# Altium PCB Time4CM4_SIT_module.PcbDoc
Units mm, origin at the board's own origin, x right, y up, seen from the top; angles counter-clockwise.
Board outline 11.4 x 15 mm, 4 copper layers (Top Layer, Int1 (GND), Int2 (PWR), Bottom Layer), stack 1.56 mm thick; 13 components, 16 nets, 71 pads, 34 vias.
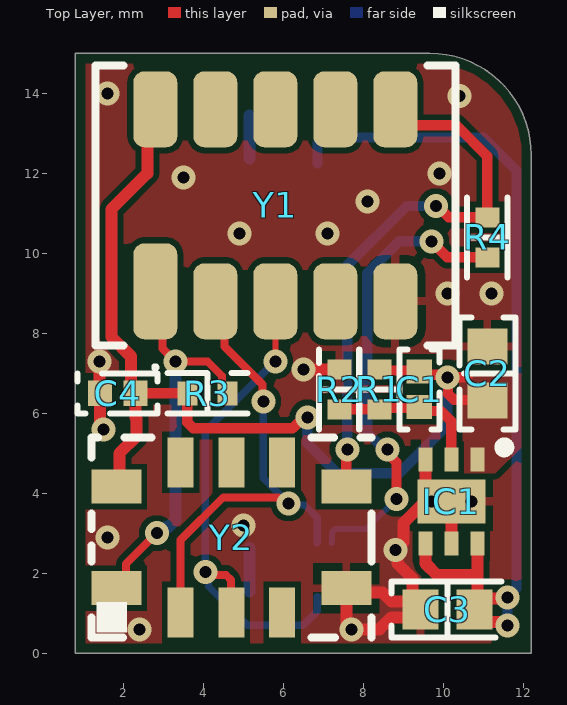
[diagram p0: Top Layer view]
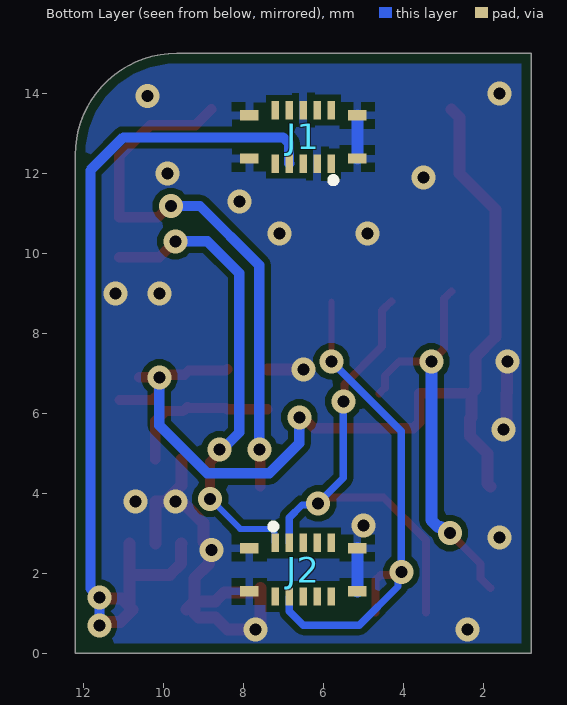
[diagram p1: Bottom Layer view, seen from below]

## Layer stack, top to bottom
Top Solder: solder mask 0.0254, SM-001, Dk 4
Top Layer: signal copper 0.035
Dielectric 1: prepreg 0.055, PP-017, Dk 4.3
Dielectric 2: prepreg 0.055, PP-017, Dk 4.3
Int1 (GND): signal copper 0.035
Dielectric 3: core 1.2, Core-039, Dk 4.8
Int2 (PWR): signal copper 0.035
Dielectric 4: prepreg 0.055, PP-017, Dk 4.3
Dielectric 5: prepreg 0.055, PP-017, Dk 4.3
Bottom Layer: signal copper 0.035
Bottom Solder: solder mask 0.0254, SM-001, Dk 4

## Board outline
0.8,0 0.8,15 9.66,15 cw(c9.66,12.46) 12.2,12.46 12.2,0

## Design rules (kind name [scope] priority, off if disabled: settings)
AcuteAngle [All] p1: minimum=3.50000000000000E+0001 checktracksonly=FALSE
BoardOutlineClearance "BoardOutlineClearance 1" [All] p1: gap=0.25 ignorepadtopadclearanceinfootprint=FALSE except(0: Arc-SplitContinuation Track-SplitContinuation SMDPad-SplitContinuation THPad-SplitContinuation Via-SplitContinuation Fill-SplitContinuation Poly-SplitContinuation Region-SplitContinuation Text-SplitContinuation) // Milling
BoardOutlineClearance "BoardOutlineClearance 2" [All] p2: gap=0.4 ignorepadtopadclearanceinfootprint=FALSE except(0: Arc-SplitContinuation Track-SplitContinuation SMDPad-SplitContinuation THPad-SplitContinuation Via-SplitContinuation Fill-SplitContinuation Poly-SplitContinuation Region-SplitContinuation Text-SplitContinuation) // V-Cut
Clearance "Clearance 3 Oz" [All] p1 off: gap=0.35 ignorepadtopadclearanceinfootprint=FALSE except(0.25: Arc-Hole Track-Hole SMDPad-Hole THPad-Hole Via-Hole Fill-Hole Poly-Hole Region-Hole Text-Hole)
Clearance "Clearance 2 Oz" [All] p2 off: gap=0.3 ignorepadtopadclearanceinfootprint=FALSE except(0.25: Arc-Hole Track-Hole SMDPad-Hole THPad-Hole Via-Hole Fill-Hole Poly-Hole Region-Hole Text-Hole)
Clearance "Clearance-1 1 Oz" [All] p3 off: gap=0.2 ignorepadtopadclearanceinfootprint=FALSE except(0.25: Arc-Hole Track-Hole SMDPad-Hole THPad-Hole Via-Hole Fill-Hole Poly-Hole Region-Hole Text-Hole) // Standart
Clearance "Clearance-2 1 Oz" [All] p4 off: gap=0.15 ignorepadtopadclearanceinfootprint=FALSE except(0.2: Arc-Fill Arc-Poly Track-Fill Track-Poly SMDPad-Fill SMDPad-Poly THPad-Fill THPad-Poly Via-Fill Via-Poly Fill-Fill Fill-Poly Poly-Poly; 0.25: Arc-Hole Track-Hole SMDPad-Hole THPad-Hole Via-Hole Fill-Hole Poly-Hole Region-Hole Text-Hole) // Advance
Clearance "Clearance-1 1/2 Oz" [All] p5 off: gap=0.125 ignorepadtopadclearanceinfootprint=FALSE except(0.2: Arc-Fill Arc-Poly Track-Fill Track-Poly SMDPad-SMDPad SMDPad-Fill SMDPad-Poly THPad-Fill THPad-Poly Via-Fill Via-Poly Fill-Fill Fill-Poly Poly-Poly Poly-Region Poly-Text; 0.25: Arc-Hole Track-Hole SMDPad-Hole THPad-Hole Via-Hole Fill-Hole Poly-Hole Region-Hole Text-Hole) // Standart
Clearance "Clearance-2 1/2 Oz" [All] p6: gap=0.1 ignorepadtopadclearanceinfootprint=FALSE except(0.15: Arc-Fill Arc-Poly Track-Fill Track-Poly SMDPad-SMDPad SMDPad-Fill SMDPad-Poly THPad-Fill THPad-Poly Via-Fill Via-Poly Fill-Fill Fill-Poly Poly-Poly Poly-Region Poly-Text; 0.25: Arc-Hole Track-Hole SMDPad-Hole THPad-Hole Via-Hole Fill-Hole Poly-Hole Region-Hole Text-Hole) // Advance
DiffPairsRouting "DiffPairsRouting 1 Oz" [All] p1: maxlimit=0.254 minlimit=0.2 mostfreqgap=0.254 toplayer_minwidth=0.2 toplayer_maxwidth=0.381 toplayer_prefwidth=0.381 midlayer1_minwidth=0.2 midlayer1_maxwidth=0.381 midlayer1_prefwidth=0.381 midlayer2_minwidth=0.2 midlayer2_maxwidth=0.381 midlayer2_prefwidth=0.381 bottomlayer_minwidth=0.2 bottomlayer_maxwidth=0.381 bottomlayer_prefwidth=0.381 maxuncoupledlength=12.7
DiffPairsRouting "DiffPairsRouting 1/2 Oz" [All] p2: maxlimit=0.254 minlimit=0.1 mostfreqgap=0.254 toplayer_minwidth=0.1 toplayer_maxwidth=0.381 toplayer_prefwidth=0.381 midlayer1_minwidth=0.1 midlayer1_maxwidth=0.381 midlayer1_prefwidth=0.381 midlayer2_minwidth=0.1 midlayer2_maxwidth=0.381 midlayer2_prefwidth=0.381 bottomlayer_minwidth=0.1 bottomlayer_maxwidth=0.381 bottomlayer_prefwidth=0.381 maxuncoupledlength=12.7
HoleSize "Minimum HoleSize" [IsPad] p1: absolutevalues=TRUE maxlimit=5.9 minlimit=0.6 maxpercent=80.000 minpercent=20.000
HoleSize "Minimum HoleSize VIA 1" [IsVia] p2: absolutevalues=TRUE maxlimit=5.9 minlimit=0.3 maxpercent=80.000 minpercent=20.000 // Standart
HoleSize "Minimum HoleSize VIA 2" [IsVia] p3: absolutevalues=TRUE maxlimit=5.9 minlimit=0.2 maxpercent=80.000 minpercent=20.000 // Advance
HoleToHoleClearance Hole2HoleClearance [All] p1: gap=0.25 allowstackedmicrovias=FALSE
MinimumAnnularRing "Minimum AR VIA Standart" [IsVia] p1: minimumring=0.15
MinimumAnnularRing "Minimum AR PAD Standart" [IsPAD] p2: minimumring=0.2
MinimumAnnularRing "Minimum AR VIA Advance" [IsVia] p3: minimumring=0.1
MinimumAnnularRing "Minimum AR PAD Advance" [IsPAD] p4: minimumring=0.15
MinimumSolderMaskSliver "SolderMask Bridge Standart" [All] p1: minsoldermaskwidth=0.15 // All Masks
MinimumSolderMaskSliver "SolderMask Bridge Advance" [All] p2: minsoldermaskwidth=0.1 // Mask LDI
PlaneClearance "PlaneClearance 3 Oz" [All] p1: clearance=0.35
PlaneClearance "PlaneClearance 2 Oz" [All] p2: clearance=0.3
PlaneClearance "PlaneClearance 1 Oz" [All] p3: clearance=0.2
PlaneClearance "PlaneClearance-1 1/2 Oz" [All] p4: clearance=0.2 // Standart
PlaneClearance "PlaneClearance-2 1/2 Oz" [All] p5: clearance=0.15 // Advance
PlaneConnect "TermalConnect 3 Oz" [All] p1: planeconnectstyle=Relief reliefexpansion=0.2 reliefentries=4 reliefconductorwidth=0.35 reliefairgap=0.35 // Standart
PlaneConnect "TermalConnect 2 Oz" [All] p2: planeconnectstyle=Relief reliefexpansion=0.2 reliefentries=4 reliefconductorwidth=0.3 reliefairgap=0.3 // Standart
PlaneConnect "TermalConnect-1 1 Oz" [All] p3: planeconnectstyle=Relief reliefexpansion=0.2 reliefentries=4 reliefconductorwidth=0.2 reliefairgap=0.2 // Standart
PlaneConnect "TermalConnect-2 1 Oz" [All] p4: pad.planeconnectstyle=Relief pad.reliefexpansion=0.15 pad.reliefentries=4 pad.reliefconductorwidth=0.2 pad.reliefairgap=0.2 via.planeconnectstyle=Direct via.reliefexpansion=0.15 via.reliefentries=4 via.reliefconductorwidth=0.15 via.reliefairgap=0.15 // Advance
PlaneConnect "TermalConnect-1 1/2 Oz" [All] p5: planeconnectstyle=Relief reliefexpansion=0.2 reliefentries=4 reliefconductorwidth=0.2 reliefairgap=0.2 // Standart
PlaneConnect "TermalConnect-2 1/2 Oz" [All] p6: pad.planeconnectstyle=Relief pad.reliefexpansion=0.15 pad.reliefentries=4 pad.reliefconductorwidth=0.15 pad.reliefairgap=0.15 via.planeconnectstyle=Direct via.reliefexpansion=0.15 via.reliefentries=4 via.reliefconductorwidth=0.15 via.reliefairgap=0.15 // Advance
PolygonConnect "PolygonConnect 3 Oz" [All] p1 off: thpad.connectstyle=Relief thpad.reliefconductorwidth=0.35 thpad.reliefentries=4 thpad.polygonreliefangle="90 Angle" thpad.airgapwidth=0.35 smdpad.connectstyle=Relief smdpad.reliefconductorwidth=0.35 smdpad.reliefentries=4 smdpad.polygonreliefangle="90 Angle" smdpad.airgapwidth=0.35 via.connectstyle=Direct via.reliefconductorwidth=0.254 via.reliefentries=4 via.polygonreliefangle="90 Angle" via.airgapwidth=0.254
PolygonConnect "PolygonConnect 2 Oz" [All] p2 off: thpad.connectstyle=Relief thpad.reliefconductorwidth=0.3 thpad.reliefentries=4 thpad.polygonreliefangle="90 Angle" thpad.airgapwidth=0.3 smdpad.connectstyle=Relief smdpad.reliefconductorwidth=0.3 smdpad.reliefentries=4 smdpad.polygonreliefangle="90 Angle" smdpad.airgapwidth=0.3 via.connectstyle=Direct via.reliefconductorwidth=0.254 via.reliefentries=4 via.polygonreliefangle="90 Angle" via.airgapwidth=0.254
PolygonConnect "PolygonConnect-1 1 Oz" [All] p3 off: thpad.connectstyle=Relief thpad.reliefconductorwidth=0.2 thpad.reliefentries=4 thpad.polygonreliefangle="90 Angle" thpad.airgapwidth=0.2 smdpad.connectstyle=Relief smdpad.reliefconductorwidth=0.2 smdpad.reliefentries=4 smdpad.polygonreliefangle="90 Angle" smdpad.airgapwidth=0.2 via.connectstyle=Direct via.reliefconductorwidth=0.254 via.reliefentries=4 via.polygonreliefangle="90 Angle" via.airgapwidth=0.254 // Standart
PolygonConnect "PolygonConnect-2 1 Oz" [All] p4 off: thpad.connectstyle=Relief thpad.reliefconductorwidth=0.15 thpad.reliefentries=4 thpad.polygonreliefangle="90 Angle" thpad.airgapwidth=0.15 smdpad.connectstyle=Relief smdpad.reliefconductorwidth=0.15 smdpad.reliefentries=4 smdpad.polygonreliefangle="90 Angle" smdpad.airgapwidth=0.15 via.connectstyle=Direct via.reliefconductorwidth=0.254 via.reliefentries=4 via.polygonreliefangle="90 Angle" via.airgapwidth=0.254 // Advance
PolygonConnect "PolygonConnect-1 1/2 Oz" [All] p5: thpad.connectstyle=Relief thpad.reliefconductorwidth=0.15 thpad.reliefentries=4 thpad.polygonreliefangle="90 Angle" thpad.airgapwidth=0.2 smdpad.connectstyle=Relief smdpad.reliefconductorwidth=0.2 smdpad.reliefentries=4 smdpad.polygonreliefangle="90 Angle" smdpad.airgapwidth=0.2 via.connectstyle=Direct via.reliefconductorwidth=0.254 via.reliefentries=4 via.polygonreliefangle="90 Angle" via.airgapwidth=0.254 // Standart
PolygonConnect "PolygonConnect-2 1/2 Oz" [All] p6: thpad.connectstyle=Relief thpad.reliefconductorwidth=0.125 thpad.reliefentries=4 thpad.polygonreliefangle="90 Angle" thpad.airgapwidth=0.15 smdpad.connectstyle=Relief smdpad.reliefconductorwidth=0.125 smdpad.reliefentries=4 smdpad.polygonreliefangle="90 Angle" smdpad.airgapwidth=0.15 via.connectstyle=Direct via.reliefconductorwidth=0.254 via.reliefentries=4 via.polygonreliefangle="90 Angle" via.airgapwidth=0.254 // Advance
RoutingCorners [All] p1 off: cornerstyle=45-Degree minsetback=2.54 maxsetback=2.54
RoutingVias [All] p1: holewidth=0.3 width=0.6 viastyle="Through Hole" minholewidth=0.2 minwidth=0.4 maxholewidth=0.5 maxwidth=1
SilkToSilkClearance Silk2SilkClearance [All] p1 off: silktosilkclearance=0.15
SilkToSolderMaskClearance Silk2SolderMaskClearance [IsPad] p1 off: minsilkscreentomaskgap=0.15 clearancetoexposedcopper=TRUE
SolderMaskExpansion SolderMaskExpansion-1 [All] p1: expansion=0.05 istentingtop=FALSE // Standart
SolderMaskExpansion "SolderMaskExpansion LDI" [All] p2: expansion=0.025 istentingtop=FALSE // Advance
UnRoutedNet [All] p1: checkbadconnections=TRUE
Width "Width 3 Oz" [All] p1 off: maxlimit=10 minlimit=0.35 preferedwidth=0.4 checkconnectedcopper=TRUE
Width "Width 2 Oz" [All] p2 off: maxlimit=10 minlimit=0.3 preferedwidth=0.35 minimp=50.000000 maximp=50.000000 favimp=50.000000 checkconnectedcopper=TRUE
Width "Width 1 Oz" [All] p3 off: maxlimit=10 minlimit=0.15 preferedwidth=0.2 checkconnectedcopper=TRUE
Width "Width 1/2 Oz" [All] p4: maxlimit=0.5 minlimit=0.1 preferedwidth=0.125 checkconnectedcopper=TRUE
20 further rules are at their usual default settings.

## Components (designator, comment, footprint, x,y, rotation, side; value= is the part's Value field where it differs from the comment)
C1 "10 pF NC" "CAP 0402_1005" 9.4,6.6 r90 top
C2 "10 µF" "CAP 0603_1608" 11.1,7 r270 top
C3 "10 µF" "CAP 0603_1608" 10.1,1.1 r0 top
C4 "0.1 µF" "CAP 0402_1005" 1.86,6.5 r0 top
IC1 "TLV76701DRVR" SON65P200X200X80-7N 10.2,3.8 r270 top
J1 "BM23FR0.8-10DP-0.35V(895)" BM23FR0810DP035V895 6.5,12.91 r0 bottom locked
J2 "BM23FR0.8-10DP-0.35V(895)" BM23FR0810DP035V895 6.5,2.09 r180 bottom locked
R1 "160 kOhms" "YAGEO RES 0402_1005" 8.4,6.6 r90 top
R2 "499 kOhms" "YAGEO RES 0402_1005" 7.4,6.6 r270 top
R3 "100 kOhms" "YAGEO RES 0402_1005" 4.1,6.5 r0 top
R4 "0 Ohms" "YAGEO RES 0402_1005" 11.1,10.4 r90 top
Y1 "SiT5711A-KW-0001" EMERALD_9070_10PINS_2022 5.8,11.2 r90 top
Y2 "SIT5503AB-WW-33E0-10.00000" Ceramic_QFN_7050_10pins 4.7,2.9 r90 top

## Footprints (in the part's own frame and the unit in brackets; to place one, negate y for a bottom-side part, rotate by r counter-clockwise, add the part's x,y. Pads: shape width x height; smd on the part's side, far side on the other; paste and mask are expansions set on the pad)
BM23FR0810DP035V895 [mm]
  rect 0.18x0.46 smd: 1(-0.7,0.67) 2(-0.7,-0.67) 3(-0.35,0.67) 4(-0.35,-0.67) 5(0,0.67) 6(0,-0.67) 7(0.35,0.67) 8(0.35,-0.67) 9(0.7,0.67) 10(0.7,-0.67)
  rect 0.47x0.26 smd: MP1(-1.35,0.54) MP2(-1.35,-0.54) MP3(1.35,0.54) MP4(1.35,-0.54)
  silkscreen extent -0.8,1.03 -0.7,1.13, body extent -1.73,-0.88 1.73,0.88, height 0.74
"CAP 0402_1005" [mm] "Chip Capacitor, 2-Leads, Body 1.02x0.51mm, IPC Medium Density"
  rect 0.6x0.64 smd: 1(-0.44,0) 2(0.44,0)
  silkscreen extent -1,-0.5 1,0.5, body extent -0.5,-0.26 0.5,0.26, height 0.52
"CAP 0603_1608" [mm] "Chip Capacitor, 2-Leads, Body 1.60x0.80mm, IPC Medium Density"
  rect 0.9x1 smd: 1(-0.675,0) 2(0.675,0)
  silkscreen extent -1.4,-0.7 1.4,0.7, body extent -0.8,-0.41 0.8,0.41, height 0.82
Ceramic_QFN_7050_10pins [mm]
  rect 0.85x1.25 smd: 1(-1.27,2.875) 5(-1.27,-2.875) 6(1.27,-2.875) 10(1.27,2.875)
  rect 1.25x0.65 smd: 2(-1.875,1.27) 3(-1.875,0) 4(-1.875,-1.27) 7(1.875,-1.27) 8(1.875,0) 9(1.875,1.27)
  silkscreen extent -2.5,-3.5 2.5,3.5, body extent -2.5,-3.5 2.5,3.5, height 2.05
EMERALD_9070_10PINS_2022 [mm]
  rrect50% 2.4x1.1 smd: 1(-2.15,3)
  rrect50% 1.9x1.1 smd: 2(-2.4,1.5) 3(-2.4,0) 4(-2.4,-1.5) 5(-2.4,-3) 6(2.4,-3) 7(2.4,-1.5) 8(2.4,0) 9(2.4,1.5) 10(2.4,3)
  silkscreen extent -4.1,-4.5 3.5,4.5, body extent -3.5,-4.5 3.5,4.5, height 5.68
SON65P200X200X80-7N [mm]
  rect 0.6x0.35 smd: 1(-1.05,0.65) 2(-1.05,0) 3(-1.05,-0.65) 4(1.05,-0.65) 5(1.05,0) 6(1.05,0.65)
  rect 1.1x1.7 smd: 7(0,0)
  silkscreen extent -1.47,1.2 -1.23,1.45, body extent -1.05,-1 1.05,1, height 0.8
"YAGEO RES 0402_1005" [mm] "Chip Resistor, 2-Leads, Body 1.0x0.5mm"
  rect 0.5x0.6 smd: 1(-0.5,0) 2(0.5,0)
  silkscreen extent -1,-0.51 1,0.51, body extent -0.5,-0.25 0.5,0.25, height 0.35

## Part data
C1: library part CC0402KRNPO9BN100, "CAP CER 10PF 50V C0G/NPO 0402", Capacitance="10 pF", Device Package="0402 (1005 Metric)", Manufacturer=Yageo, Operating Temperature="-55°C ~ 125°C", Supplier Part Number 1=13-CC0402KRNPO9BN100CT-ND, Temperature Coefficient="C0G, NP0", Tolerance=±10%, Voltage - Rated=50V
C2 C3: library part CC0603MPX5R5BB106, "CAP CER 10UF 6.3V X5R 0603", Device Package="0603 (1608 Metric)", Manufacturer=Yageo, Operating Temperature="-55°C ~ 85°C", Supplier Part Number 1=13-CC0603MPX5R5BB106CT-ND, Temperature Coefficient=X5R, Tolerance=±20%, Voltage - Rated=6.3V
C4: library part CC0402KRX7R5BB104, "CAP CER 0.1UF 6.3V X7R 0402", Device Package="0402 (1005 Metric)", Manufacturer=Yageo, Operating Temperature="-55°C ~ 125°C", Supplier Part Number 1=311-1701-1-ND, Temperature Coefficient=X7R, Tolerance=±10%, Voltage - Rated=6.3V
IC1: "IC REG LINEAR POS ADJ 1A 6WSON", Manufacturer_Name="Texas Instruments", Mouser Part Number=595-TLV76701DRVR
J1 J2: library part BM23FR0.8-10DS-0.35V_895_, "Connector", Manufacturer_Name=Hirose, Manufacturer_Part_Number=BM23FR0.8-10DS-0.35V(895), Mouser Part Number=798-3FR0810DS035V895
R1: library part RC0402FR-07160KL, "RES 160K OHM 1% 1/16W 0402", Device Package="0402 (1005 Metric)", Manufacturer=Yageo, Operating Temperature="-55°C ~ 155°C", Power (Watts)="0.063W, 1/16W", Supplier Device Package=0402, Supplier Part Number 1=YAG2996CT-ND, Temperature Coefficient=±100ppm/°C, Tolerance=±1%
R2: library part RC0402FR-07499KL, "RES 499K OHM 1% 1/16W 0402", Device Package="0402 (1005 Metric)", Manufacturer=Yageo, Operating Temperature="-55°C ~ 155°C", Power (Watts)="0.063W, 1/16W", Supplier Device Package=0402, Supplier Part Number 1=311-499KLRCT-ND, Temperature Coefficient=±100ppm/°C, Tolerance=±1%
R3: library part RC0402FR-07100KL, "RES 100K OHM 1% 1/16W 0402", Device Package="0402 (1005 Metric)", Manufacturer=Yageo, Operating Temperature="-55°C ~ 155°C", Power (Watts)="0.063W, 1/16W", Supplier Device Package=0402, Supplier Part Number 1=311-100KLRCT-ND, Temperature Coefficient=±100ppm/°C, Tolerance=±1%
R4: library part RC0402FR-070RL, "RES 0 OHM JUMPER 1/16W 0402", Device Package="0402 (1005 Metric)", Manufacturer=Yageo, Operating Temperature="-55°C ~ 155°C", Power (Watts)="0.063W, 1/16W", Supplier Device Package=0402, Supplier Part Number 1=311-0.0LRCT-ND, Tolerance=Jumper
Y1 Y2: "Crystal or Oscillator", Manufacturer_Name=SiTime

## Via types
v1: diameter 0.6, hole 0.3, Top Layer to Bottom Layer, 34 vias

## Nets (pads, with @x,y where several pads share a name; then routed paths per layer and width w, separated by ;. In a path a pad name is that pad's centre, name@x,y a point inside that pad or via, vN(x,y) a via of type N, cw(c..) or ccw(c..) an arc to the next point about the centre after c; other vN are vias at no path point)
1V8: J1.5
3V3: J1.1
5V: C3.2 IC1.4 IC1.6 J1.7 | length 22.8
  Top Layer w0.3: IC1.4 9.556,2.744 9.556,2.244 9.838,1.963 10.85,1.963 ; IC1.6 10.85,1.963 ; v1(11.6,0.7) 11.573,0.7 11.489,0.784 11.075,0.784 10.775,1.084 C3.2 C3.2@10.85,1.175 ; v1(11.6,1.4) 11.573,1.4 11.539,1.366 11.041,1.366 C3.2@10.85,1.175 ; C3.2@10.85,1.175 10.85,1.963
  Bottom Layer w0.25: J1.7 6.86,12.25 6.86,12.754 7.006,12.9 11,12.9 11.825,12.075 11.825,1.625 v1(11.6,1.4) v1(11.6,0.7)
10MHz: J2.1 R4.1 | length 11.7
  Top Layer w0.254: v1(8.6,5.1) 8.6,5.009 8.831,4.778 v1(8.831,3.864) ; v1(9.7,10.3) 10.1,9.9 R4.1
  Bottom Layer w0.15: J2.1 7.215,2.775 7.215,3.024 7.303,3.112 8.08,3.112 v1(8.831,3.864)
  Bottom Layer w0.254: v1(8.6,5.1) 8.522,5.1 8.1,5.522 8.1,9.5 8.9,10.3 v1(9.7,10.3)
GND: C2.1 C3.1 C4.1 IC1.3 IC1.5 IC1.7 J1.3 J1.6 J1.MP1 J1.MP2 J1.MP3 J1.MP4 J2.MP1 J2.MP2 J2.MP3 J2.MP4 R2.1 Y1.5 Y2.5 | length 15.9
  Top Layer w0.3: v1(1.4,7.3) 1.406,7.294 1.406,6.514 C4.1 1.42,5.761 1.5,5.681 v1(1.5,5.6) ; v1(6.5,7.1) R2.1 ; IC1.3 9.55,4.2 9.825,3.925 9.95,3.8 IC1.7 IC1.5 ; v1(9.7,3.8) 9.6,3.7 9.445,3.7 9,3.255 9,2.781 v1(8.8,2.581) 8.857,2.524 8.857,2.243 9.226,1.874 C3.1@9.226,1.299 ; C3.1@9.226,1.299 8.701,1.299 8.474,1.526 7.679,1.526 Y2.5 7.575,0.752 7.7,0.627 v1(7.7,0.6) 8.4,0.6 8.701,0.901 9.125,0.901 9.226,1.001 C3.1@9.226,1.299 ; C3.1@9.226,1.299 C3.1 C3.1@9.226,1.299
  Bottom Layer w0.3: J2.MP4 J2.MP3 ; J1.MP1 J1.MP2
  other v1: 2.4,0.6 1.6,2.9 5,3.2 10.7,3.8 10.1,9 11.2,9 4.9,10.5 7.1,10.5 8.1,11.3 3.5,11.9 9.9,12 10.4,13.933 1.6,14
GPIO_1: J1.8
GPIO_2: J1.9
GPIO_3: J1.10
NetC1_1: C1.1 IC1.2 R1.1 R2.2 | length 3.9
  Top Layer w0.254: R2.2 R1.1 8.43,6.13 9.37,6.13 C1.1 9.505,6.055 9.945,6.055 10.2,5.8 IC1.2
NetJ1_2: J1.2
NetJ1_4: J1.4
NetR3_2: R3.2 Y1.1 Y2.1 | length 10.1
  Top Layer w0.2: Y2.1 2.07,1.875 2.07,2.238 v1(2.837,3.004) ; Y1.1 2.978,8.872 2.978,7.622 v1(3.3,7.3) 4.1,7.3 4.463,6.937 4.463,6.637 R3.2
  Bottom Layer w0.3: v1(2.837,3.004) 2.918,3.004 3.068,3.154 3.124,3.154 3.3,3.33 v1(3.3,7.3)
NetR4_2: R4.2 Y1.6 Y2.6 | length 14.1
  Top Layer w0.254: Y2.6 7.575,5.075 v1(7.6,5.1) ; Y1.6 9.2,13.2 10.328,13.2 11.1,12.428 R4.2 10.134,10.9 9.852,11.182 v1(9.813,11.182)
  Bottom Layer w0.254: v1(7.6,5.1) 7.6,9.7 9.082,11.182 v1(9.813,11.182)
SCL: J2.4 Y1.3 Y2.3 | length 13.1
  Top Layer w0.15: v1(5.8,7.3) Y1.3
  Top Layer w0.2: v1(4.05,2.03) 4.127,1.954 4.571,1.954 4.692,1.833 4.692,1.033 Y2.3
  Bottom Layer w0.18: v1(5.8,7.3) 4.05,5.55 v1(4.05,2.03) 4.131,1.949 4.131,1.669 5.1,0.7 6.5,0.7 6.85,1.05 J2.4
SDA: J2.3 Y1.2 Y2.2 | length 12.3
  Top Layer w0.2: Y2.2 3.43,2.83 4.5,3.9 5.872,3.9 6.022,3.75 v1(6.13,3.75) ; Y1.2 4.532,8.568 4.532,7.668 5.476,6.724 5.476,6.324 v1(5.5,6.3)
  Bottom Layer w0.18: v1(5.5,6.3) 5.5,4.38 v1(6.13,3.75) 6.171,3.709 6.532,3.709 6.85,3.392 J2.3
VDD: C1.2 C2.2 C4.2 IC1.1 R1.2 R3.1 Y1.10 Y2.10 | length 25.3
  Top Layer w0.254: C4.2@2.45,6.5 R3.1 3.6,5.776 3.749,5.627 6.233,5.627 6.506,5.9 v1(6.6,5.9) ; R1.2 8.43,7.07 9.37,7.07 9.474,6.966 10.034,6.966 v1(10.1,6.9) ; 10.6,6.9 v1(10.1,6.9) ; C2.2@11.09,6.335 10.269,6.335 10.12,6.484 10.12,6.88 v1(10.1,6.9)
  Top Layer w0.3: Y2.10 1.9,4.245 1.9,5 2.33,5.43 2.33,5.871 2.3,5.901 C4.2 2.193,6.607 2.193,7.42 1.7,7.913 1.7,11.1 2.6,12 2.6,13.4 Y1.10
  Bottom Layer w0.254: v1(6.6,5.9) 6.6,5.248 7.348,4.5 8.9,4.5 10.102,5.702 10.102,6.898 v1(10.1,6.9)
pads on no net: J2.2 J2.5 J2.6 J2.7 J2.8 J2.9 J2.10 Y1.4 Y1.7 Y1.8 Y1.9 Y2.4 Y2.7 Y2.8 Y2.9

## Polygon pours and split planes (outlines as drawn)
GND on Top Layer "NONET_L-01_P-001" (solid, pour order 2): 0,15 13,15 13,0 0,0
VDD on Top Layer "NONET_L-01_P-001" (solid, pour order 0): 11.3,4.5 12,5.2 12,7 10.4,7 10.4,4.5
GND on Bottom Layer "NONET_L-01_P-001" (solid, pour order 1): 0,15 13,15 13,0 0,0

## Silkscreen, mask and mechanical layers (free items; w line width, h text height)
Top Overlay:
  rectangle: 1.33,0.526 2.092,1.288
OUTLINE:
  the board outline again, w0.102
